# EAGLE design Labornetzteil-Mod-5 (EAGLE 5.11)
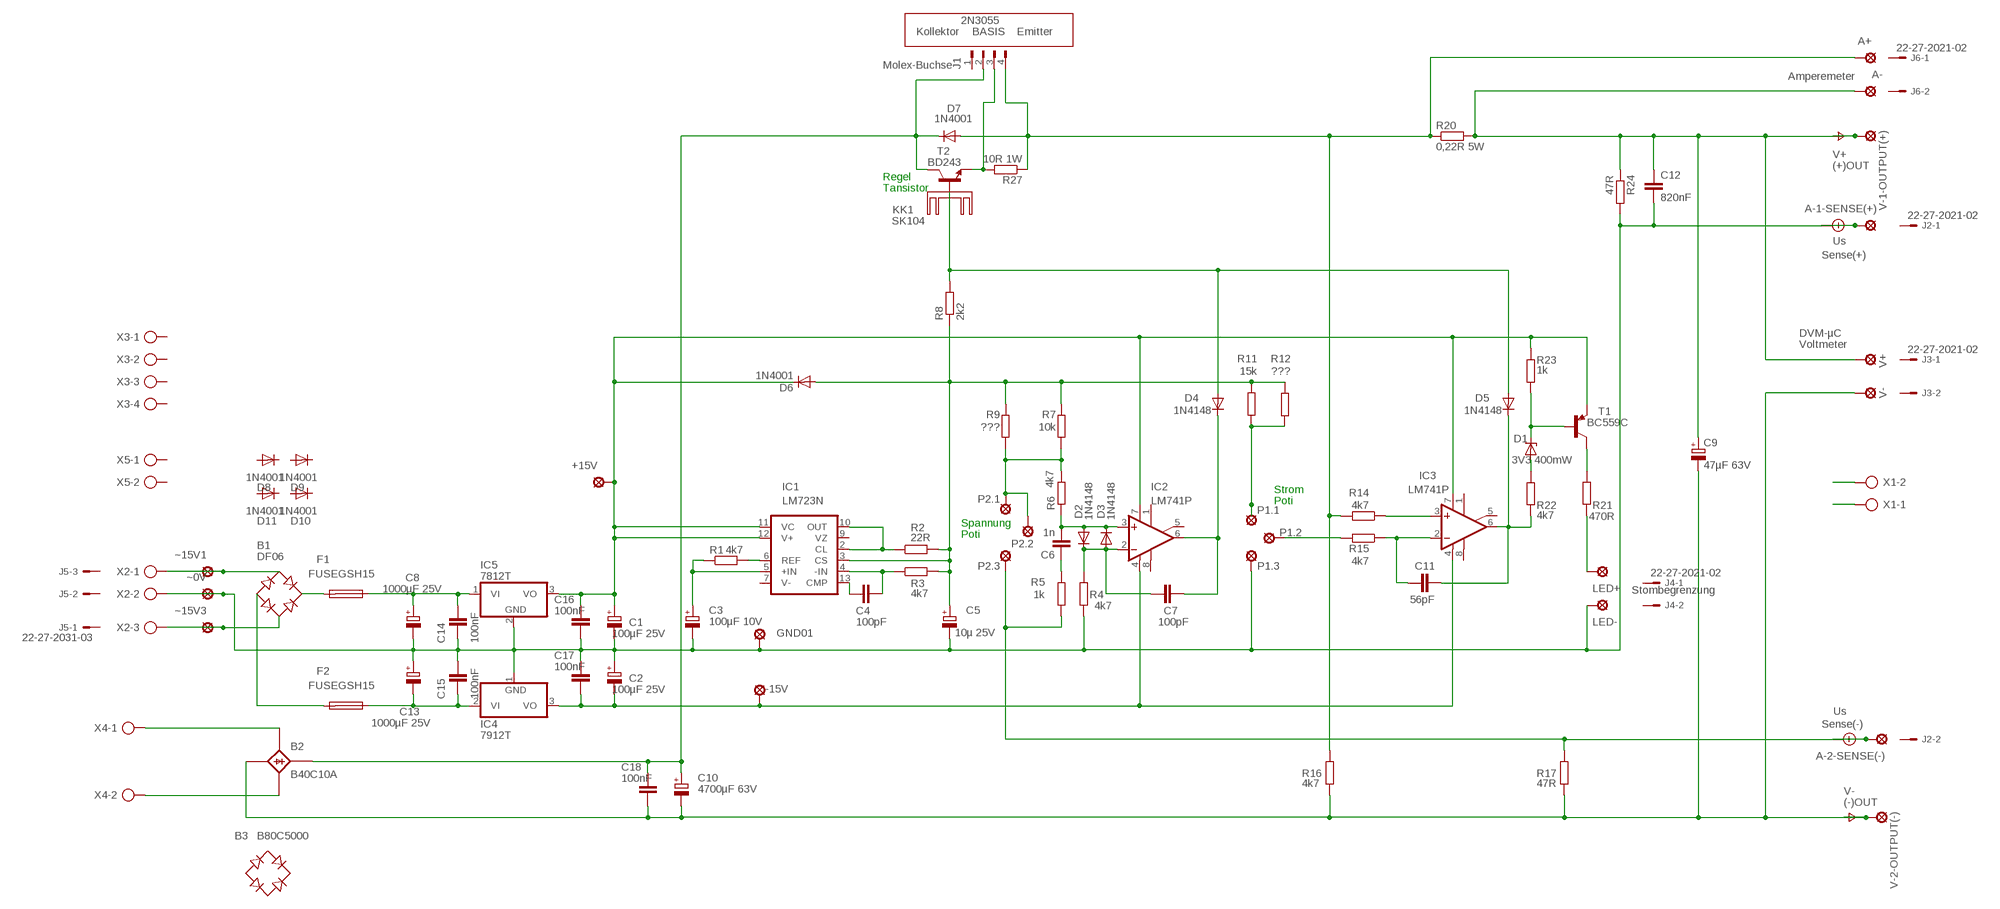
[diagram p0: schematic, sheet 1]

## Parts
+15V  SE14  [SE14]
-15V  SE14  [SE14]
A+  SE14  [SE14]
A-  SE14  [SE14]
A-1-SENSE(+)  SE14  [SE14]
A-2-SENSE(-)  SE14  [SE14]
B1  DF06  B-DIL  [B-DIL]
B2  B40C10A  B25A-  [B25A-]
B3  B80C5000  RECTIFIER-SKB32  [SKB32]
C1  100µF 25V  CPOL-EUE5-8.5  [E5-8,5]
C2  100µF 25V  CPOL-EUE5-8.5  [E5-8,5]
C3  100µF 10V  CPOL-EUE5-8.5  [E5-8,5]
C4  100pF  C-EU025-024X044  [C025-024X044]
C5  10µ 25V  CPOL-EUE5-8.5  [E5-8,5]
C6  1n  C-EU025-024X044  [C025-024X044]
C7  100pF  C-EU025-024X044  [C025-024X044]
C8  1000µF 25V  CPOL-EUE5-8.5  [E5-8,5]
C9  47µF 63V  CPOL-EUE3.5-8  [E3,5-8]
C10  4700µF 63V  CPOL-EUE10-35  [EB35D]
C11  56pF  C-EU025-024X044  [C025-024X044]
C12  820nF  C-EU025-024X044  [C025-024X044]
C13  1000µF 25V  CPOL-EUE5-8.5  [E5-8,5]
C14  100nF  C-EU025-030X050  [C025-030X050]
C15  100nF  C-EU025-030X050  [C025-030X050]
C16  100nF  C-EU025-030X050  [C025-030X050]
C17  100nF  C-EU025-030X050  [C025-030X050]
C18  100nF  C-EU025-030X050  [C025-030X050]
D1  3V3 400mW  ZENER-DIODEDO34-7  [DO34Z7]
D2  1N4148  1N4148DO35-10  [DO35-10]
D3  1N4148  1N4148DO35-10  [DO35-10]
D4  1N4148  1N4148DO35-10  [DO35-10]
D5  1N4148  1N4148DO35-10  [DO35-10]
D6  1N4001  1N4004  [DO41-10]
D7  1N4001  1N4004  [DO41-10]
D8  1N4001  1N4004  [DO41-10]
D9  1N4001  1N4004  [DO41-10]
D10  1N4001  1N4004  [DO41-10]
D11  1N4001  1N4004  [DO41-10]
F1  FUSEGSH15  [GSH15]
F2  FUSEGSH15  [GSH15]
GND01  SE14  [SE14]
IC1  LM723N  [DIL14]
IC2  LM741P  [DIL08]
IC3  LM741P  [DIL08]
IC4  7912T  7915T  [TO220H]
IC5  7812T  7815T  [TO220H]
J1  FLOPPY-4  [FLOPPY-4]
J2  22-27-2021-02  [6410-02]
J3  22-27-2021-02  [6410-02]
J4  22-27-2021-02  [6410-02]
J5  22-27-2031-03  [6410-03]
J6  22-27-2021-02  [6410-02]
KK1  SK104  [SK104]
LED+  SE14  [SE14]
LED-  SE14  [SE14]
P1.1  SE14  [SE14]
P1.2  SE14  [SE14]
P1.3  SE14  [SE14]
P2.1  SE14  [SE14]
P2.2  SE14  [SE14]
P2.3  SE14  [SE14]
R1  4k7  R-EU_0204/2V  [0204V]
R2  22R  R-EU_0204/2V  [0204V]
R3  4k7  R-EU_0204/2V  [0204V]
R4  4k7  R-EU_0207/10  [0207/10]
R5  1k  R-EU_0207/10  [0207/10]
R6  4k7  R-EU_0207/10  [0207/10]
R7  10k  R-EU_0207/10  [0207/10]
R8  2k2  R-EU_0207/10  [0207/10]
R9  ???  R-EU_0207/10  [0207/10]
R11  15k  R-EU_0207/10  [0207/10]
R12  ???  R-EU_0207/10  [0207/10]
R14  4k7  R-EU_0207/10  [0207/10]
R15  4k7  R-EU_0207/10  [0207/10]
R16  4k7  R-EU_0207/10  [0207/10]
R17  47R  R-EU_0207/10  [0207/10]
R20  0,22R 5W  R-EU_0617/22  [0617/22]
R21  470R  R-EU_0207/10  [0207/10]
R22  4k7  R-EU_0207/10  [0207/10]
R23  1k  R-EU_0207/10  [0207/10]
R24  47R  R-EU_0207/10  [0207/10]
R27  10R 1W  R-EU_0309/12  [0309/12]
T1  BC559C  -PNP-TO92  [TO92]
T2  BD243  [TO220]
V+  SE14  [SE14]
V-  SE14  [SE14]
V-1-OUTPUT(+)  V(+) Output  SE14  [SE14]
V-2-OUTPUT(-)  V(-) Output  SE14  [SE14]
X1  AK300/2  [AK300/2]
X2  AK300/3  [AK300/3]
X3  AK300/4  [AK300/4]
X4  AK300/2  [AK300/2]
X5  AK300/2  [AK300/2]
~0V  SE14  [SE14]
~15V1  SE14  [SE14]
~15V3  SE14  [SE14]

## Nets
+US: A-1-SENSE(+).MP C1.- C2.+ C3.- C5.- C8.- C12.2 C13.+ C14.1 C15.2 C16.1 C17.2 GND01.MP IC4.1(GND) IC5.2(GND) LED-.MP P1.3.MP R4.1 R24.2 X2.2 ~0V.MP ; supply symbol labelled Us
-US: A-2-SENSE(-).MP P2.3.MP R5.1 R17.1 ; supply symbol labelled Us
GND: B2.-1(-) C9.- C10.- C18.1 R16.2 R17.2 V-2-OUTPUT(-).MP V-.MP X1.1 ; supply symbol labelled V-
N$1: C3.+ IC1.5(+IN) R1.1
N$4: B1.AC1 X2.1 ~15V1.MP
N$5: IC1.6(REF) R1.2
N$6: -15V.MP C2.- C17.1 IC2.4(V-) IC3.4(V-) IC4.3(VO)
N$7: C6.1 R5.2
N$8: P2.1.MP P2.2.MP R6.2 R7.1 R9.1
N$9: IC1.2(CL) IC1.10(OUT) R2.1
N$10: C4.2 IC1.4(-IN) R3.1
N$12: C4.1 IC1.13(CMP)
N$13: LED+.MP R21.1
N$14: C5.+ D6.A IC1.3(CS) R2.2 R3.2 R7.2 R8.1 R9.2 R11.2 R12.1
N$15: C6.2 D2.A D3.C IC2.3(+IN) R6.1
N$16: C7.1 D2.C D3.A IC2.2(-IN) R4.2
N$17: D4.A D5.A R8.2 T2.1(B)
N$18: C7.2 D4.C IC2.6(OUT)
N$19: P1.1.MP R11.1 R12.2
N$20: B1.AC2 X2.3 ~15V3.MP
N$21: R21.2 T1.3(C)
N$22: IC3.3(+IN) R14.1
N$23: D1.C R23.2 T1.2(B)
N$24: P1.2.MP R15.2
N$25: D1.A R22.1
N$27: A+.MP D7.A J1.4 R14.2 R16.1 R20.1 R27.1
N$31: B2.AC1-(AC1) X4.1
N$32: B2.AC2-(AC2) X4.2
N$33: C11.1 IC3.2(-IN) R15.1
N$34: C11.2 D5.C IC3.6(OUT) R22.2
N$35: +15V.MP C1.+ C16.2 D6.C IC1.11(VC) IC1.12(V+) IC2.7(V+) IC3.7(V+) IC5.3(VO) R23.1 T1.1(E)
N$37: B2.+1(+) C10.+ C18.2 D7.C J1.2 T2.2(C)
N$38: C8.+ C14.2 F1.1 IC5.1(VI)
N$39: B1.- F2.2
N$40: C13.- C15.1 F2.1 IC4.2(VI)
N$41: B1.+ F1.2
N$42: J1.3 R27.2 T2.3(E)
V+: A-.MP C9.+ C12.1 R20.2 R24.1 V+.MP V-1-OUTPUT(+).MP X1.2
Unconnected: B2.+ B2.- B2.AC1 B2.AC2 B3.+ B3.- B3.AC1 B3.AC2 D8.A D8.C D9.A D9.C D10.A D10.C D11.A D11.C IC1.7(V-) IC1.9(VZ) IC2.1(ON1) IC2.5(ON2) IC2.8(OPT) IC3.1(ON1) IC3.5(ON2) IC3.8(OPT) J1.1 J2.1 J2.2 J3.1 J3.2 J4.1 J4.2 J5.1 J5.2 J5.3 J6.1 J6.2 X3.1 X3.2 X3.3 X3.4 X5.1 X5.2

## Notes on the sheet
- 2N3055
- Kollektor | BASIS | Emitter
- Molex-Buchse
- Amperemeter
- (+)OUT
- Regel
- Tansistor
- Sense(+)
- DVM-µC
- Voltmeter
- Strom
- Poti
- Spannung
- Poti
- Stombegrenzung
- Sense(-)
- (-)OUT

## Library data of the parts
+15V -15V A+ A- A-1-SENSE(+) A-2-SENSE(-) GND01 LED+ LED- P1.1-P1.3 P2.1-P2.3 V+ V- V-1-OUTPUT(+) V-2-OUTPUT(-) ~0V ~15V1 ~15V3 = solpad:SE14: SOLDER PAD
B1 = rectifier:B-DIL: RECTIFIER
B2 = rectifier:B25A-: RECTIFIER 25-A bridge
B3 = rectifier:RECTIFIER-: Rectifier
C1-C3 C5 C8-C10 C13 = rcl:CPOL-EU: POLARIZED CAPACITOR, European symbol
C4 C6 C7 C11 C12 C14-C18 = rcl:C-EU: CAPACITOR, European symbol
D1 = diode:ZENER-DIODE: Z-Diode
D2-D5 = diode:1N4148: DIODE
D6-D11 = diode:1N4004: DIODE
F1 F2 = fuse:FUSE: Fuse; OC_FARNELL: unknown; OC_NEWARK: unknown
IC1 = linear:*723: Positive VOLTAGE REGULATOR
IC2 IC3 = linear:*741: OP AMP
IC4 = linear:79*: Negative VOLTAGE REGULATOR
IC5 = linear:78*: Positive VOLTAGE REGULATOR Source: http://cache.national.com/ds/LM/LM78L05.pdf http://www.fairchildsemi.com/ds/LM/LM7805.pdf
J1 = con-amp:FLOPPY-4: MATE N-LOCK Floppy / HDD conector Distributor: Bürklin 71F970; OC_FARNELL: unknown; OC_NEWARK: unknown
J2-J4 J6 = con-molex:22-?-02: CONNECTOR; OC_FARNELL: unknown; OC_NEWARK: unknown
J5 = con-molex:22-?-03: CONNECTOR wire to board 2.54 mm (.1 inch) pitch header; OC_FARNELL: unknown; OC_NEWARK: unknown
KK1 = heatsink:SK104: HEATSINK
R1-R9 R11 R12 R14-R17 R20-R24 R27 = rcl:R-EU_: RESISTOR, European symbol
T1 = transistor:*-PNP-: PNP Transistror
T2 = transistor:BD243: NPN TRANSISTOR Source: Motorola Semiconductor, Master Selection Guide Q3/95 SG73 REV 8 page 5.5-4
X1 X4 X5 = con-ptr500:AK300/2: CONNECTOR; OC_FARNELL: unknown; OC_NEWARK: unknown
X2 = con-ptr500:AK300/3: CONNECTOR; OC_FARNELL: unknown; OC_NEWARK: unknown
X3 = con-ptr500:AK300/4: CONNECTOR; OC_FARNELL: unknown; OC_NEWARK: unknown

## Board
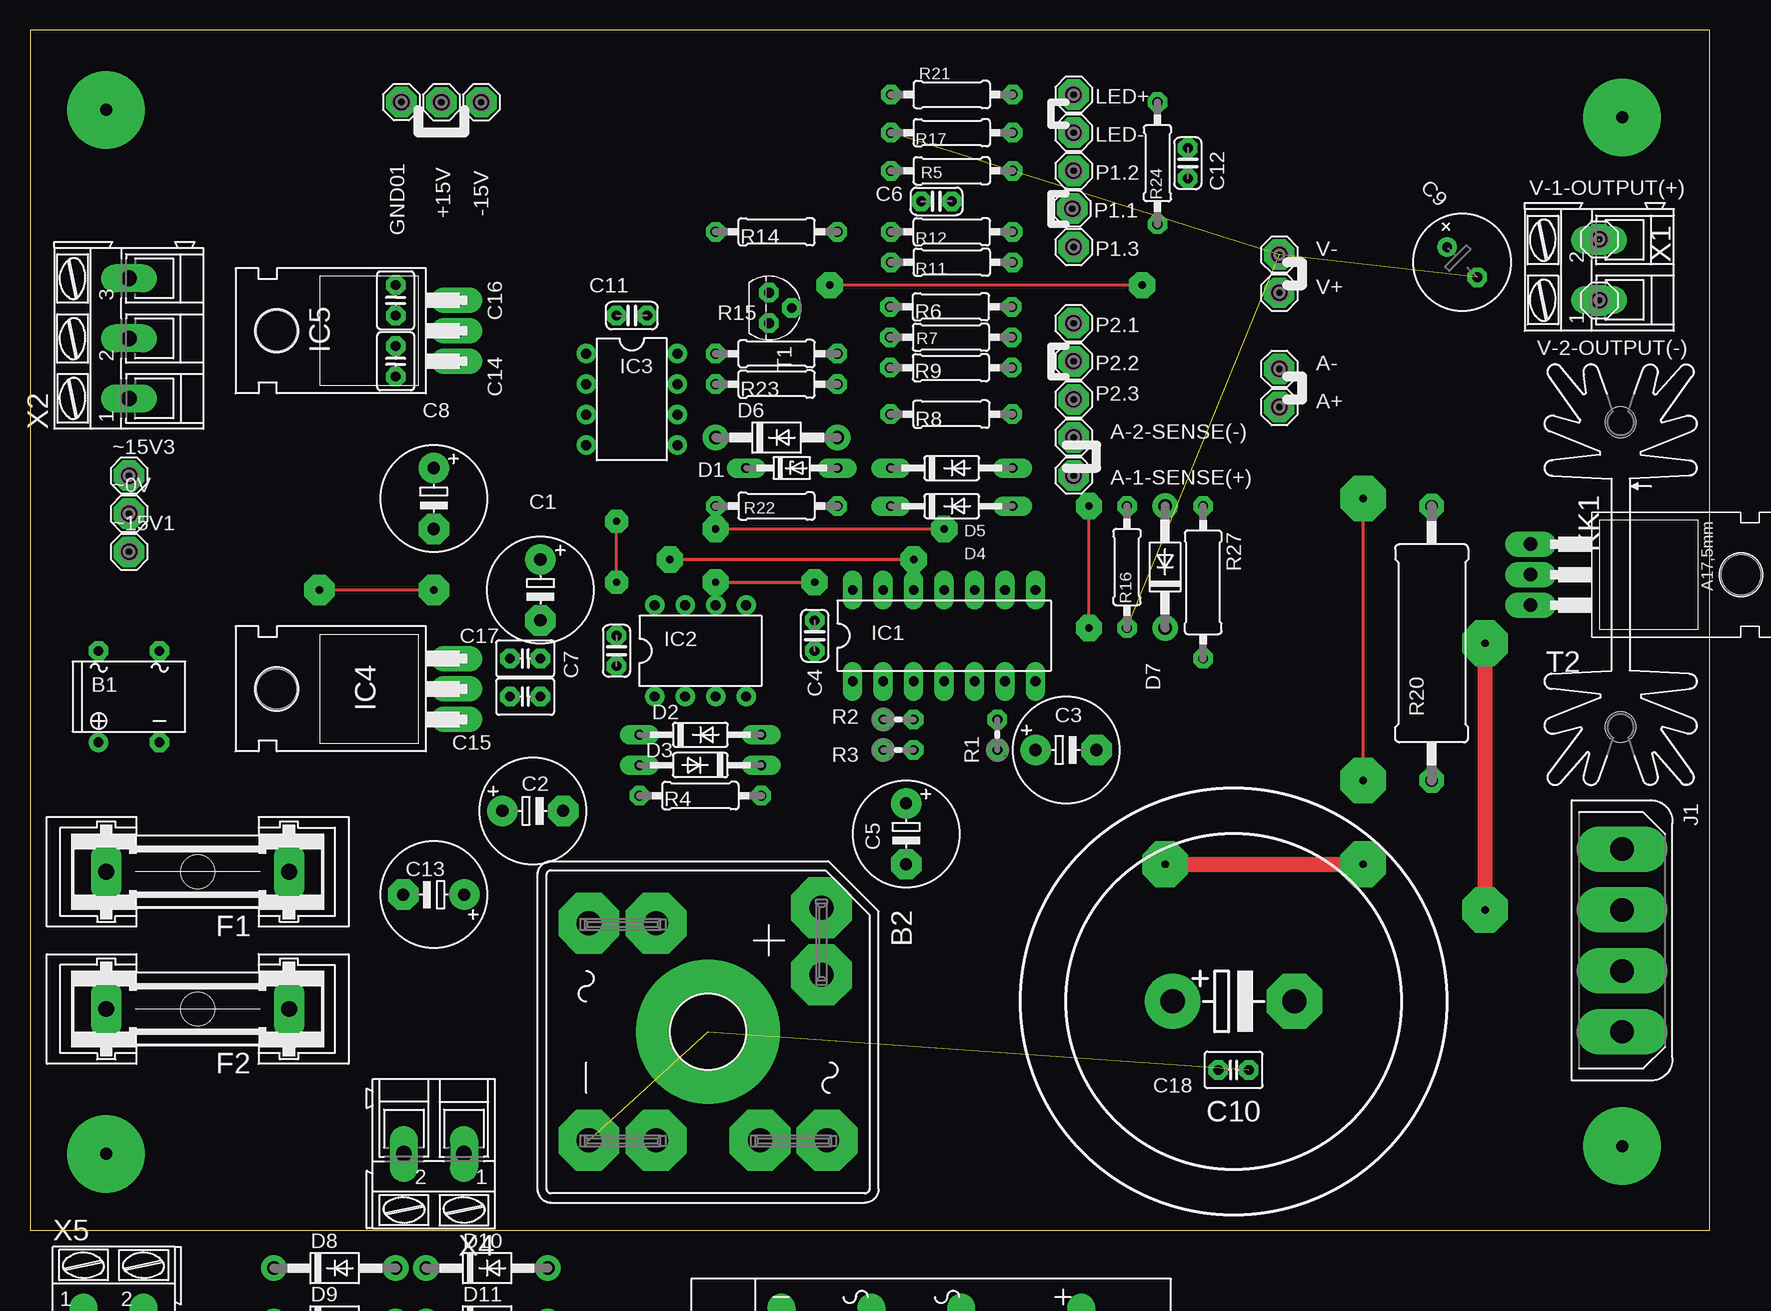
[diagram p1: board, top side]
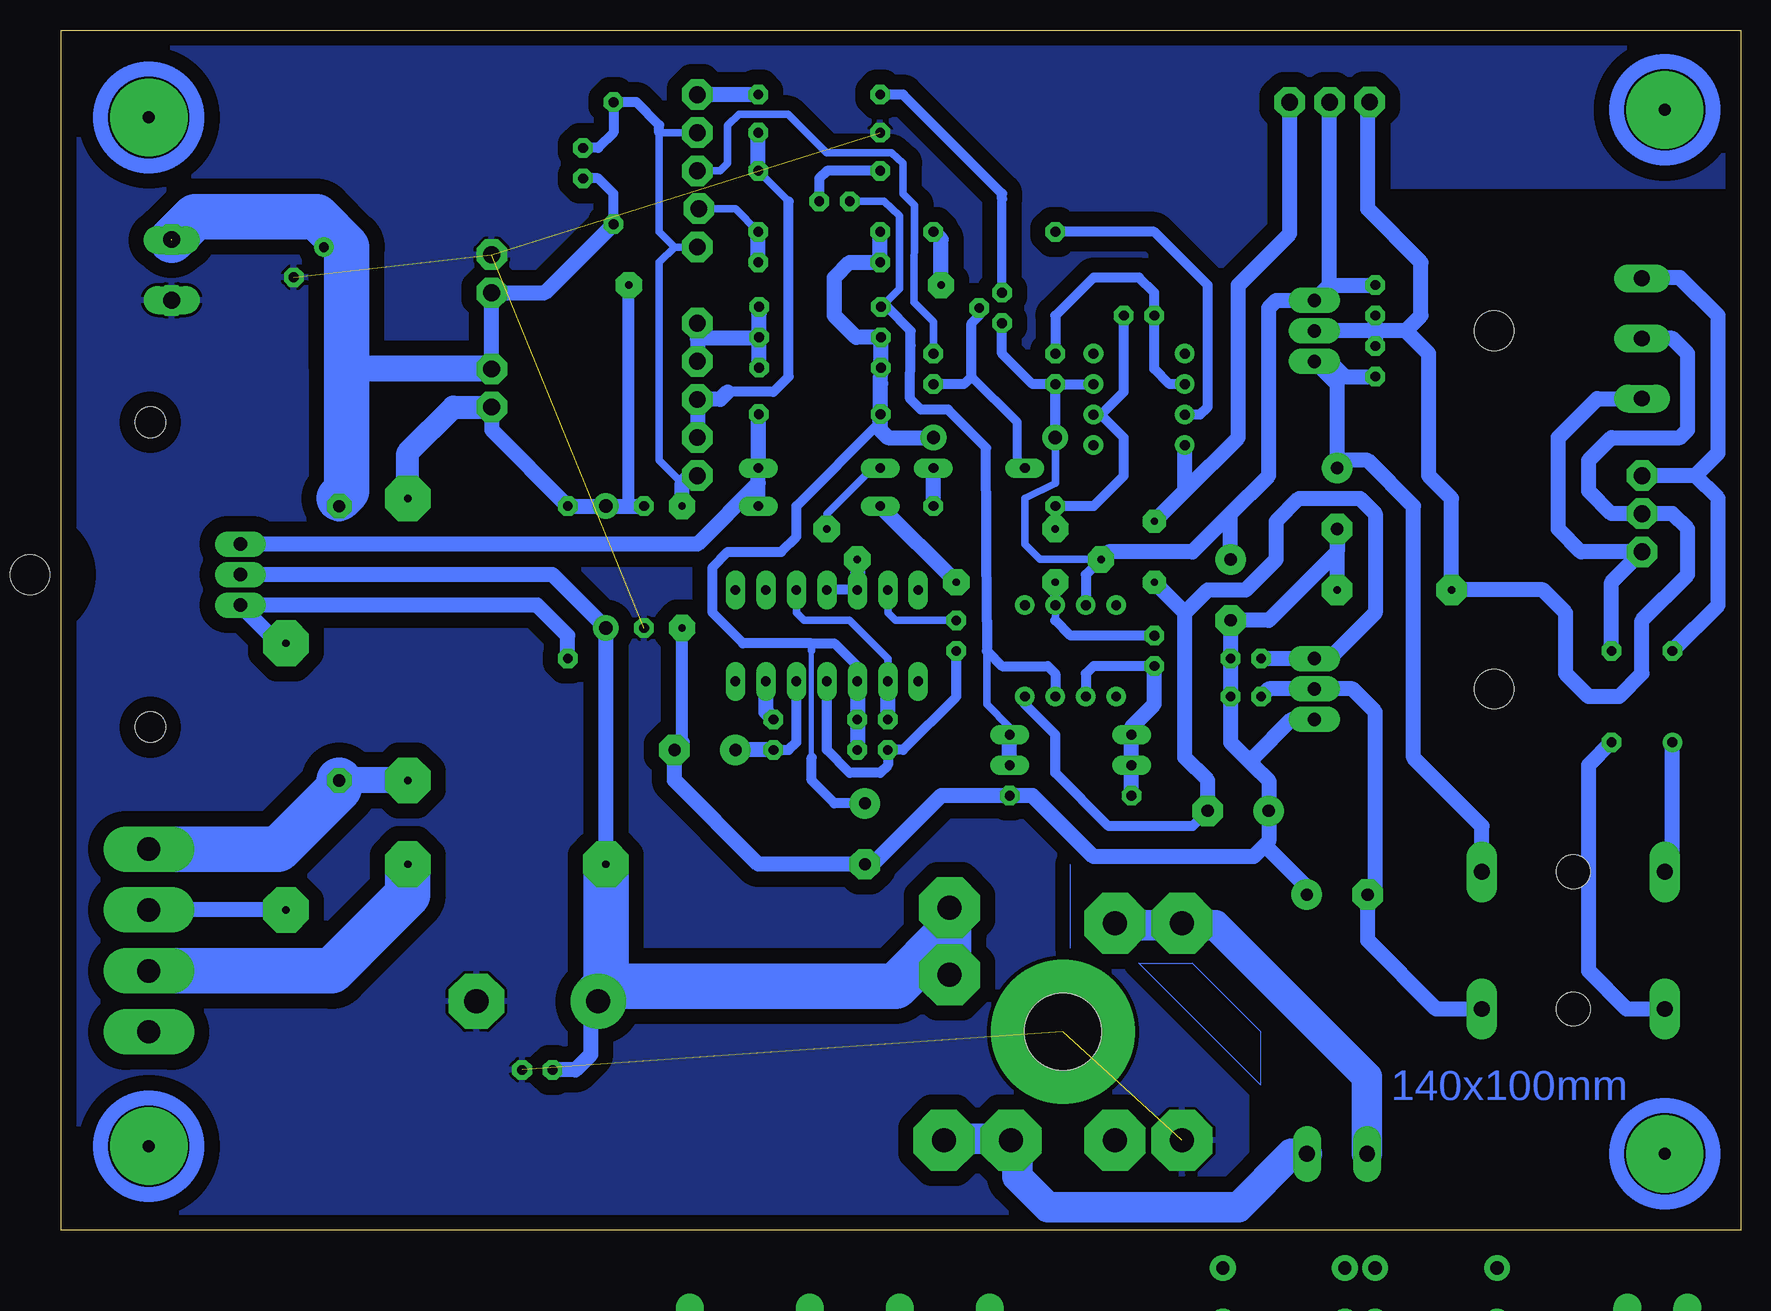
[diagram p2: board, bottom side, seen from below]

Size 140 x 100 mm. Coordinates in mm from the lower left corner, seen from the top.
Outline: 0,0 140,0 140,100 0,100 0,0
Copper layers (1*16): Top 0.035mm / dielectric 1.5mm / Bottom 0.035mm
Design rules "default *": minimum track width 30mil, minimum drill 24mil, track to track 8mil, track to pad 8mil, pad to pad 8mil, via to via 8mil, smd to smd 8mil, copper to edge 0.5mm, drill to drill 8mil, minimum pad ring 10mil, minimum via ring 8mil, stop-mask expansion 4mil, vias tented up to drill 0mil, thermal gap 10mil

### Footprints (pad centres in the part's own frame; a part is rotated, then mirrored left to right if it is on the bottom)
SE14 = drill 1.397 pad 2.54 octagon: MP 0,0
B-DIL = drill 0.813 round: + -2.54,-3.81 | drill 0.813 octagon: - 2.54,-3.81; AC1 2.54,3.81; AC2 -2.54,3.81
B25A- = drill 2.007 pad 5.08 octagon: + -10.338,9.449; +1 -4.75,9.449; - 9.042,-4.343; -1 9.042,-9.931; AC1 9.042,4.343; AC1- 9.042,9.931; AC2 -9.042,-4.343; AC2- -9.042,-9.931 | hole 6.401: 0,0
SKB32 = drill 1.321 long: + -13.97,0; - 11.024,0; AC1 -3.962,0; AC2 3.531,0
E5-8,5 = drill 1.016 pad 2.54 round: + -2.54,0 | drill 1.016 pad 2.54 octagon: - 2.54,0
C025-024X044 = drill 0.813 octagon: 1 -1.27,0; 2 1.27,0
E3,5-8 = drill 0.813 pad 1.6 round: + -1.778,0 | drill 0.813 pad 1.6 octagon: - 1.778,0
EB35D = drill 2.007 pad 4.597 round: + -5.08,0 | drill 2.007 pad 4.597 octagon: - 5.08,0
C025-030X050 = drill 0.813 octagon: 1 -1.27,0; 2 1.27,0
DO34Z7 = drill 0.813 long: A 3.81,0; C -3.81,0
DO35-10 = drill 0.813 long: A 5.08,0; C -5.08,0
DO41-10 = drill 1.118 round: A 5.08,0; C -5.08,0
GSH15 = drill 1.321 pad 2.54 long: 1 -7.62,0; 2 7.62,0 | hole 2.794: 0,0
DIL14 = drill 0.813 long: 1 -7.62,-3.81; 2 -5.08,-3.81; 3 -2.54,-3.81; 4 0,-3.81; 5 2.54,-3.81; 6 5.08,-3.81; 7 7.62,-3.81; 8 7.62,3.81; 9 5.08,3.81; 10 2.54,3.81; 11 0,3.81; 12 -2.54,3.81; 13 -5.08,3.81; 14 -7.62,3.81
DIL08 = drill 0.813 pad 1.27 round: 1 -3.81,-3.81; 2 -1.27,-3.81; 3 1.27,-3.81; 4 3.81,-3.81; 5 3.81,3.81; 6 1.27,3.81; 7 -1.27,3.81; 8 -3.81,3.81
TO220H = drill 1.118 long: 1 -2.54,-10.16; 2 0,-10.16; 3 2.54,-10.16 | hole 3.302: 0,4.826
FLOPPY-4 = drill 1.93 pad 3.81 long: 1 7.62,0; 2 2.54,0; 3 -2.54,0; 4 -7.62,0
6410-02 = drill 1.016 long: 1 1.27,0; 2 -1.27,0
6410-03 = drill 1.016 long: 1 2.54,0; 2 0,0; 3 -2.54,0
SK104 = hole 2.54: -12.7,-0.762; 12.7,-0.762
0204V = drill 0.813 octagon: 1 -1.27,0; 2 1.27,0
0207/10 = drill 0.813 octagon: 1 -5.08,0; 2 5.08,0
0617/22 = drill 1.016 octagon: 1 -11.43,0; 2 11.43,0
0309/12 = drill 0.813 octagon: 1 -6.35,0; 2 6.35,0
TO92 = drill 0.813 octagon: 1 1.27,0; 2 0,1.905; 3 -1.27,0
TO220 = drill 1.118 long: 1 -2.54,-6.35; 2 0,-6.35; 3 2.54,-6.35 | hole 3.302: 0,11.176
AK300/2 = drill 1.321 long: 1 -2.515,0; 2 2.489,0
AK300/3 = drill 1.321 long: 1 -5.004,0; 2 0,0; 3 5.004,0
AK300/4 = drill 1.321 long: 1 -7.493,0; 2 -2.515,0; 3 2.515,0; 4 7.493,0

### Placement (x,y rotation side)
+15V  34.29,93.98 0 top
-15V  37.61,93.98 0 top
A+  104.14,68.58 0 top
A-  104.14,71.75 0 top
A-1-SENSE(+)  87,62.87 0 top
A-2-SENSE(-)  87,66.04 0 top
B1  8.26,44.45 0 top
B2  56.52,16.51 270 top
B3  not placed on the board
C1  42.55,53.34 270 top
C2  41.91,34.92 0 top
C3  86.36,40.01 0 top
C4  65.41,49.53 270 top
C5  73.03,33.02 270 top
C6  75.56,85.72 180 top
C7  48.9,48.26 90 top
C8  33.66,60.96 270 top
C9  119.38,80.64 315 top
C10  100.33,19.05 0 top
C11  50.16,76.2 0 top
C12  96.52,88.9 90 top
C13  33.66,27.94 180 top
C14  30.48,72.39 270 top
C15  41.27,44.45 0 top
C16  30.48,77.47 90 top
C17  41.27,47.62 0 top
C18  100.33,13.34 180 top
D1  63.5,63.5 0 top
D2  55.88,41.27 0 top
D3  55.88,38.73 180 top
D4  76.83,60.33 0 top
D5  76.83,63.5 0 top
D6  62.23,66.04 0 top
D7  94.61,55.24 90 top
D8  not placed on the board
D9  not placed on the board
D10  not placed on the board
D11  not placed on the board
F1  13.97,29.84 180 top
F2  13.97,18.41 180 top
GND01  30.96,93.99 0 top
IC1  76.2,49.53 0 top
IC2  55.88,48.26 0 top
IC3  50.16,69.22 270 top
IC4  25.4,45.09 90 top
IC5  25.4,74.93 90 top
J1  132.72,24.13 270 top
J2  not placed on the board
J3  not placed on the board
J4  not placed on the board
J5  not placed on the board
J6  not placed on the board
KK1  133.35,54.61 270 top
LED+  87,94.61 0 top
LED-  87,91.44 0 top
P1.1  86.88,85.11 0 top
P1.2  87,88.27 0 top
P1.3  87,81.92 0 top
P2.1  87,75.56 0 top
P2.2  87,72.39 0 top
P2.3  87,69.22 0 top
R1  80.64,41.27 90 top
R2  72.39,42.55 0 top
R3  72.39,40.01 0 top
R4  55.88,36.2 180 top
R5  76.83,88.27 180 top
R6  76.77,76.94 0 top
R7  76.77,74.39 180 top
R8  76.8,67.99 0 top
R9  76.77,71.86 180 top
R11  76.83,80.64 180 top
R12  76.83,83.19 0 top
R14  62.23,83.19 0 top
R15  62.23,73.03 0 top
R16  91.44,55.24 270 top
R17  76.83,91.44 180 top
R20  116.84,48.9 90 top
R21  76.83,94.61 180 top
R22  62.23,60.33 180 top
R23  62.23,70.48 0 top
R24  93.98,88.9 90 top
R27  97.79,53.98 270 top
T1  61.59,76.83 270 top
T2  131.44,54.61 270 top
V+  104.14,78.11 0 top
V-  104.14,81.28 0 top
V-1-OUTPUT(+)  130.81,82.55 0 top
V-2-OUTPUT(-)  130.81,77.47 0 top
X1  130.81,80.01 90 top
X2  8.26,74.3 90 top
X3  not placed on the board
X4  33.66,6.35 180 top
X5  not placed on the board
~0V  8.26,59.69 0 top
~15V1  8.26,56.52 0 top
~15V3  8.26,62.87 0 top

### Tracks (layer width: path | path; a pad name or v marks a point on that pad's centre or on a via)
+US  (via drill 0.61 pad 2.18, 0.61 pad 2.54)
  Top 0.254: v88.27,50.16 v88.27,60.33 | v24.13,53.34 v33.66,53.34
  Bottom 0.61: LED-.MP 90.17,91.44 90.17,83.19 88.9,81.92 | 88.9,81.92 P1.3.MP | 88.9,81.92 90.17,80.64 90.17,64.14 88.27,62.23
  Bottom 0.813: 90.17,91.44 90.17,92.08 92.08,93.98 R24.2 93.98,91.44 95.25,90.17 C12.2
  Bottom 1.016: 88.27,40.64 v88.27,50.16
  Bottom 1.27: 39.69,32.07 39.37,32.38 C2.+ 39.37,37.47 40.64,38.73 | 39.69,32.07 40.64,31.11 53.98,31.11 59.05,36.2 R4.1 66.67,36.2 72.39,30.48 C5.- 81.92,30.48 88.9,37.47 C3.- 88.27,40.64 | 40.64,38.73 42.55,40.64 C15.2 C17.2 C1.- 39.37,50.8 33.66,56.52 C8.- v33.66,53.34 | 30.48,74.93 C14.1 | 30.48,74.93 C16.1 | 30.48,74.93 IC5.2 | C13.+ 36.2,28.57 39.69,32.07 | 30.96,93.82 GND01.MP 31.11,93.83 31.11,85.09 26.67,80.64 26.67,76.2 27.94,74.93 | 27.94,74.93 30.48,74.93 | v88.27,60.33 88.27,62.23 87.63,62.87 A-1-SENSE(+).MP | IC4.1 37.47,42.55 40.64,39.37 40.64,38.73 | 27.94,74.93 26.04,73.03 26.04,62.87 24.13,60.96 v24.13,53.34 16.51,53.34 14.61,51.44 14.61,46.35 12.7,44.45 10.16,44.45 8.26,46.35 8.26,50.8 4.45,54.61 4.45,58.42 5.71,59.69 ~0V.MP 10.79,59.69 12.7,61.59 12.7,64.14 10.79,66.04 5.08,66.04 4.45,66.67 4.45,73.03 5.71,74.3 X2.2
-US
  Bottom 0.61: 79.38,85.72 R5.1
  Bottom 0.813: 84.45,69.85 80.64,69.85 79.38,71.12 79.38,85.72
  Bottom 1.27: R5.1 R17.1 | 84.45,69.85 85.09,69.22 P2.3.MP A-2-SENSE(-).MP
GND  (via drill 0.1 pad 12)  (5 unrouted)
  other vias: 56.52,16.51
  pour Bottom (isolate 1.27): -1.27,100.97 -1.27,87 29.84,87 29.21,29.21 41.27,29.21 41.27,0 141.6,-1.27 141.6,101.6
N$1
  Bottom 0.813: IC1.5 78.74,40.64 79.38,40.01 R1.1
  Bottom 1.27: R1.1 C3.+
N$2
  Bottom 0: 50.16,22.23 45.72,22.23 40.01,16.51 40.01,12.06 50.16,22.23
N$3
  Bottom 0: 55.88,23.5 55.88,30.48
N$4
  Bottom 1.27: B1.AC1 10.79,53.98 ~15V1.MP 13.34,56.52 15.24,58.42 15.24,66.04 11.99,69.29 X2.1
N$5
  Bottom 1.27: R1.2 81.28,43.18 IC1.6
N$6  (via drill 0.61 pad 1.93)
  Top 0.254: v48.9,59.05 v48.9,53.98 48.9,53.34
  Bottom 0.813: C2.- 45.72,33.66 52.7,33.66 57.15,38.1 57.15,41.27 59.69,43.81 IC2.4
  Bottom 1.27: C2.- 44.45,37.47 46.35,39.37 46.35,51.44 | 46.35,51.44 44.45,53.34 41.27,53.34 38.73,55.88 38.73,59.05 36.83,60.96 31.75,60.96 30.48,59.69 30.48,51.44 34.29,47.62 IC4.3 C17.1 | 46.35,61.59 IC3.4 | v48.9,59.05 46.35,61.59 | 46.35,51.44 v48.9,53.98 | -15V.MP 37.61,83.04 41.91,78.74 41.91,66.04 46.35,61.59
N$7
  Bottom 0.813: C6.1 76.83,87.63 76.2,88.27 R5.2
N$8
  Bottom 1.27: 81.84,76.91 R7.1 R9.1 | 87,74.3 P2.2.MP | 87,74.3 P2.1.MP | 81.84,76.91 R6.2 | 81.84,76.91 81.92,74.3 87,74.3
N$9
  Bottom 0.61: IC1.10 78.74,51.44 78.11,50.8 74.3,50.8 71.12,47.62 IC1.2
  Bottom 1.27: R2.1 IC1.2
N$10
  Bottom 0.813: C4.2 65.41,44.45 69.85,40.01 R3.1 71.12,38.73 71.75,38.1 74.3,38.1 76.2,40.01 IC1.4
N$11  (via drill 1 pad 6.45)
  other vias: 6.35,93.34
N$12
  Bottom 0.61: C4.1 70.48,50.8 71.12,51.44 IC1.13
N$13
  Bottom 1.27: R21.1 LED+.MP
N$14
  Bottom 0.406: 77.47,39.37 77.47,48.26
  Bottom 0.61: 77.47,48.26 77.47,48.9
  Bottom 0.813: IC1.3 73.66,46.99 75.56,48.9 77.47,48.9 83.19,48.9 85.72,51.44 85.72,55.24 84.45,56.52 80.01,56.52 78.74,57.78 78.74,60.33 71.75,67.31 | C5.+ 75.56,35.56 77.47,37.47 77.47,39.37
  Bottom 1.27: R3.2 R2.2 IC1.3 | D6.A 71.12,66.04 71.75,66.67 71.75,67.31 71.75,67.95 R8.1 71.72,70.55 R9.2 R7.2 73.76,74.39 75.56,76.2 75.56,79.38 74.3,80.64 R11.2 R12.1
N$15
  Bottom 0.61: C6.2 71.43,85.72 70.16,84.51 70.16,78.43 71.66,76.94 R6.1 | D2.A 60.96,41.91 62.87,43.81 62.87,50.8
  Bottom 0.813: 71.86,76.94 R6.1 71.58,76.83 71.12,76.83 69.22,74.93 69.22,73.71 69.27,69.27 68.36,68.36 66.09,68.36 62.92,65.18 62.87,50.8 62.87,48.26 61.59,46.99 57.78,46.99 57.15,46.35 IC2.3
  Bottom 1.27: D3.C D2.A
N$16
  Bottom 0.813: IC2.2 54.61,46.35 53.98,46.99 C7.1
  Bottom 1.27: R4.2 D3.A D2.C 50.8,41.91 48.9,43.81 C7.1
N$17
  Bottom 0.762: R8.2
  Bottom 1.27: D4.A 81.92,62.23 | 81.92,62.23 D5.A 81.88,62.91 R8.2 | T2.1 87,57.15 81.92,62.23
N$18  (via drill 0.61 pad 2.18)
  Top 0.254: v57.15,53.98 v65.41,53.98
  Bottom 0.61: 57.15,50.8 IC2.6
  Bottom 0.813: IC2.6 v57.15,53.98 | 57.15,50.8 55.88,49.53 C7.2
  Bottom 1.27: v65.41,53.98 D4.C
N$19
  Bottom 0.61: R12.2 83.82,85.09 86.86,85.09
  Bottom 1.27: R11.1 R12.2 | 86.86,85.09 P1.1.MP
N$20
  Bottom 1.27: X2.3 6.91,79.38 5.08,79.38 1.91,76.2 1.91,64.77 3.81,62.87 | B1.AC2 1.91,52.07 1.91,60.96 3.81,62.87 | 3.81,62.87 ~15V3.MP
N$21
  Bottom 0.762: T1.3 61.59,85.91 | R21.2 71.12,94.61
  Bottom 0.813: 61.59,85.91 61.59,86.36 69.85,94.61 R21.2
N$22
  Bottom 0.813: R14.1 48.9,83.19 44.45,78.74 44.45,68.58 45.09,67.94 IC3.3
N$23
  Bottom 0.762: D1.C 60.33,64.14 60.33,67.31 64.14,71.12
  Bottom 0.813: T1.2 63.5,76.2 64.14,75.56 64.14,71.12 64.77,70.48 R23.2
N$24
  Bottom 0.61: P1.2.MP 85.09,88.27 84.45,88.9 84.45,92.08 83.51,92.97 79.44,92.97 76.22,89.76 70.81,89.76 69.85,88.9 69.85,86.36 68.89,85.4 68.94,77.31 67.31,75.68 R15.2
N$25
  Bottom 1.27: R22.1 D1.A
N$26  (via drill 1 pad 6.45)
  other vias: 132.72,92.71
N$27  (via drill 0.61 pad 2.18, 0.61 pad 3.81)
  Top 0.254: v92.71,78.74 v66.67,78.74 | v111.12,37.47 v111.12,60.96
  Bottom 1.016: 92.71,60.33 v92.71,78.74
  Bottom 1.27: R16.1 92.71,60.33 D7.A R27.1 104.14,66.67 A+.MP | R14.2 66.67,82.55 v66.67,78.74
  Bottom 1.93: v111.12,60.96 111.12,64.77 107.31,68.58 A+.MP
  Bottom 2.184: v111.12,37.47 R20.1
  Bottom 3.81: J1.4 121.92,31.75 116.84,36.83 R20.1
N$28  (via drill 1 pad 6.45)
  other vias: 132.72,6.99
N$29  (via drill 1 pad 6.45)
  other vias: 6.35,6.35
N$31
  Bottom 2.54: X4.1 37.47,6.35 41.91,1.91 57.78,1.91 60.33,4.45 60.33,7.62 65.02,7.62 B2.AC1-
N$32
  Bottom 2.54: X4.2 31.17,12.75 43.81,25.4 48.01,25.4 | 48.01,25.4 50.8,25.4 | 48.01,25.4 B2.AC2-
N$33
  Bottom 0.813: IC3.2 47.62,70.48 48.9,71.75 C11.1 48.9,78.11 50.16,79.38 53.98,79.38 57.15,76.2 R15.1
N$34  (via drill 0.61 pad 2.18)
  Top 0.254: v57.15,58.42 v76.2,58.42
  Bottom 0.61: D5.C 72.39,63.5 76.2,59.69 v76.2,58.42
  Bottom 0.762: R22.2 v57.15,58.42
  Bottom 0.813: R22.2 53.98,60.33 51.44,62.87 51.44,66.04 53.34,67.94 | 53.34,67.94 IC3.6 | 53.34,67.94 51.44,69.85 C11.2
N$35  (via drill 0.61 pad 2.18)
  Top 0.254: v53.34,55.88 v73.66,55.88
  Bottom 0.61: v53.34,55.88 58.42,55.88 59.69,57.15 59.69,60.96 57.15,62.23 D6.C
  Bottom 0.813: IC1.12 IC1.11 | D6.C R23.1 | R23.1 59.05,70.48 61.59,73.03 T1.1 | R23.1 IC3.7 | IC2.7 54.61,54.61 v53.34,55.88
  Bottom 1.27: v73.66,55.88 IC1.12 | C1.+ 42.55,59.69 | v53.34,55.88 52.7,56.52 45.72,56.52 42.55,59.69 | C16.2 34.29,78.74 IC5.3 | IC5.3 38.73,77.47 39.37,76.83 39.37,62.87 42.55,59.69 | +15V.MP 34.29,78.11 IC5.3
N$37  (via drill 0.61 pad 3.81)
  Top 1.27: v94.61,30.48 v111.12,30.48
  Bottom 1.27: T2.2 99.06,54.61 D7.C v94.61,30.48 | 94.61,19.68 C10.+ 95.89,18.41 95.89,14.61 97.16,13.34 C18.2
  Bottom 3.81: C10.+ 95.25,19.68 94.61,20.32 70.48,20.32 66.04,24.77 66.04,21.34 B2.+1 | J1.2 117.47,21.59 111.12,27.94 v111.12,30.48 | 94.61,19.68 v94.61,30.48
N$38
  Bottom 1.27: C14.2 33.02,71.12 34.29,72.39 IC5.1 33.66,70.48 33.66,64.14 | 33.66,64.14 C8.+ | F1.1 21.59,33.66 27.3,39.37 27.3,60.33 31.11,64.14 33.66,64.14
N$39
  Bottom 1.27: B1.- 12.7,38.73 12.7,21.59 9.53,18.41 F2.2
N$40
  Bottom 1.27: C15.1 39.37,45.09 IC4.2 32.38,45.09 30.48,43.18 30.48,28.57 C13.- 31.11,24.13 25.4,18.41 F2.1
N$41
  Bottom 1.27: B1.+ 5.71,31.11 6.35,30.48 F1.2
N$42  (via drill 0.61 pad 3.81)
  Top 1.27: v121.28,48.9 v121.28,26.67
  Bottom 1.27: R27.2 97.79,49.53 100.33,52.07 T2.3 121.92,48.9 v121.28,48.9 | v121.28,26.67 J1.3
V+  (1 unrouted)
  Bottom 0.813: C12.1 95.25,87.63 93.98,86.36 R24.1
  Bottom 1.27: A-.MP V+.MP 99.69,78.11 R24.1 | 119.38,84.45 C9.+
  Bottom 2.184: A-.MP 116.2,71.75
  Bottom 2.54: 116.84,60.96 R20.2
  Bottom 3.81: X1.2 128.85,84.45 119.38,84.45 118.75,84.45 116.2,81.92 116.2,71.75 116.2,61.59 116.84,60.96
(copper drawn outside any net)
  shapes: Bottom circle x4

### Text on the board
Bottom: 140x100mm
bOrigins: 140x100mm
